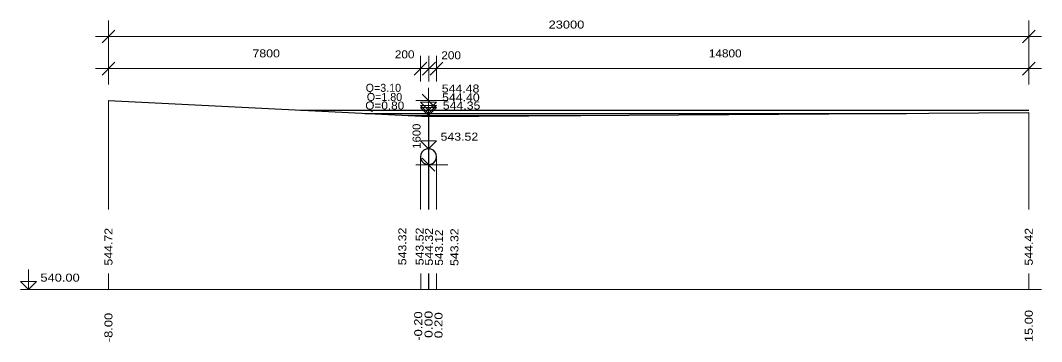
# Model space of a CAD drawing. Extents: x 7 to 442, y -393 to 441.
# Drawn here: x 171.84 to 197.36, y -181.67 to -173.65 of the extents above; entities that cross this region are included whole.
import ezdxf

# ---------------------------------------------------------------- set-up
doc = ezdxf.new("R2010")
doc.units = 0
doc.header["$LTSCALE"] = 0.08
doc.layers.add('7', color=7, linetype='Continuous', lineweight=13)

msp = doc.modelspace()

# ---------------------------------------------------------------- linework, layer by layer
at = {"layer": '7'}
for p, q in [((174.042, -175.253), (174.042, -173.653)), ((197.042, -175.253), (197.042, -173.653)), ((173.882, -174.213), (174.202, -173.893)), ((196.882, -174.213), (197.202, -173.893)), ((173.722, -174.053), (197.362, -174.053)), ((174.042, -175.173), (174.042, -174.533)), ((181.842, -175.173), (181.842, -174.533)), ((182.052, -175.173), (182.052, -174.533)), ((182.052, -175.173), (182.052, -174.533)), ((182.242, -175.173), (182.242, -174.533)), ((197.042, -175.173), (197.042, -174.533)), ((173.882, -175.013), (174.202, -174.693)), ((181.682, -175.013), (182.002, -174.693)), ((181.892, -175.013), (182.212, -174.693)), ((181.892, -175.013), (182.212, -174.693)), ((182.082, -175.013), (182.402, -174.693)), ((196.882, -175.013), (197.202, -174.693)), ((173.722, -174.853), (197.362, -174.853)), ((182.202, -175.813), (181.882, -175.493)), ((182.042, -177.413), (182.042, -175.333)), ((174.042, -178.373), (174.042, -175.653)), ((181.722, -175.653), (182.522, -175.653)), ((182.052, -178.373), (182.052, -176.053)), ((197.042, -178.373), (197.042, -175.953)), ((182.042, -176.853), (182.052, -176.853)), ((182.052, -178.373), (182.052, -176.853)), ((181.842, -178.373), (181.842, -177.053)), ((182.202, -177.413), (181.882, -177.093)), ((182.242, -178.373), (182.242, -177.053)), ((181.722, -177.253), (182.522, -177.253)), ((182.042, -178.373), (182.042, -177.253)), ((174.042, -180.373), (174.042, -179.973)), ((181.852, -180.373), (181.852, -179.973)), ((182.042, -180.373), (182.042, -179.973)), ((182.052, -180.373), (182.052, -179.973)), ((182.052, -180.373), (182.052, -179.973)), ((182.242, -180.373), (182.242, -179.973)), ((197.042, -180.373), (197.042, -179.973)), ((171.842, -180.373), (197.362, -180.373))]:
    msp.add_line(p, q, dxfattribs=at)
at = {"layer": '7', "lineweight": 25}
for p, q in [((178.844, -175.893), (197.042, -175.893)), ((180.45, -175.973), (193.984, -175.973)), ((181.535, -176.028), (185.85, -176.028))]:
    msp.add_line(p, q, dxfattribs=at)
at = {"layer": '7'}
for points in [[(182.042, -175.393), (182.042, -175.893), (181.842, -175.693), (182.242, -175.693), (182.042, -175.893)], [(182.042, -175.473), (182.042, -175.973), (181.842, -175.773), (182.242, -175.773), (182.042, -175.973)], [(182.042, -175.528), (182.042, -176.028), (181.842, -175.828), (182.242, -175.828), (182.042, -176.028)], [(182.042, -176.353), (182.042, -176.853), (181.842, -176.653), (182.242, -176.653), (182.042, -176.853)], [(172.042, -179.873), (172.042, -180.373), (171.842, -180.173), (172.242, -180.173), (172.042, -180.373)]]:
    msp.add_lwpolyline(points, dxfattribs=at)
at = {"layer": '7', "lineweight": 25}
msp.add_lwpolyline([(174.042, -175.653), (182.042, -176.053), (182.042, -176.853), (181.982, -176.863), (181.922, -176.893), (181.882, -176.933), (181.852, -176.993), (181.842, -177.053), (181.852, -177.113), (181.882, -177.173), (181.922, -177.213), (181.982, -177.243), (182.042, -177.253), (182.102, -177.243), (182.162, -177.213), (182.202, -177.173), (182.232, -177.113), (182.242, -177.053), (182.232, -176.993), (182.202, -176.933), (182.162, -176.893), (182.102, -176.863), (182.052, -176.853), (182.052, -176.053), (197.042, -175.953)], dxfattribs=at)

# ---------------------------------------------------------------- texts
at = {"layer": '7'}
for s, width, p in [('23000', 1.2, (185.042, -173.853)), ('7800', 1.15, (177.642, -174.573)), ('200', 1.1, (181.199, -174.597)), ('200', 1.1, (182.361, -174.62)), ('14800', 1.1, (189.047, -174.573)), ('544.48', 1.15, (182.371, -175.451)), ('544.40', 1.15, (182.379, -175.671)), ('Q=0.80', 1.1, (180.461, -175.875)), ('544.35', 1.15, (182.397, -175.875)), ('543.52', 1.15, (182.342, -176.653)), ('540.00', 1.2, (172.342, -180.173))]:
    msp.add_text(s, height=0.2, dxfattribs=dict(at, width=width)).set_placement(p)
for s, p in [('Q=3.10', (180.47, -175.433)), ('Q=1.80', (180.498, -175.661))]:
    msp.add_text(s, height=0.2, dxfattribs=at).set_placement(p)
for s, width, p in [('1600', 1.05, (181.842, -176.853)), ('544.72 ', 1.15, (174.142, -179.773)), ('543.32 ', 1.15, (181.486, -179.764)), ('543.52 ', 1.15, (181.919, -179.764)), ('544.32 ', 1.15, (182.152, -179.773)), ('543.12 ', 1.1, (182.403, -179.773)), ('543.32 ', 1.15, (182.788, -179.782)), ('544.42 ', 1.15, (197.142, -179.773)), (' -0.20 ', 1.2, (181.883, -181.737)), ('  0.00 ', 1.3, (182.142, -181.773)), ('  0.00 ', 1.3, (182.142, -181.773)), ('  0.00 ', 1.3, (182.142, -181.773)), (' 15.00 ', 1.2, (197.142, -181.773)), (' -8.00 ', 1.2, (174.142, -181.773)), ('  0.20 ', 1.25, (182.39, -181.773))]:
    msp.add_text(s, height=0.2, rotation=90, dxfattribs=dict(at, width=width)).set_placement(p)

doc.saveas('drawing.dxf')
